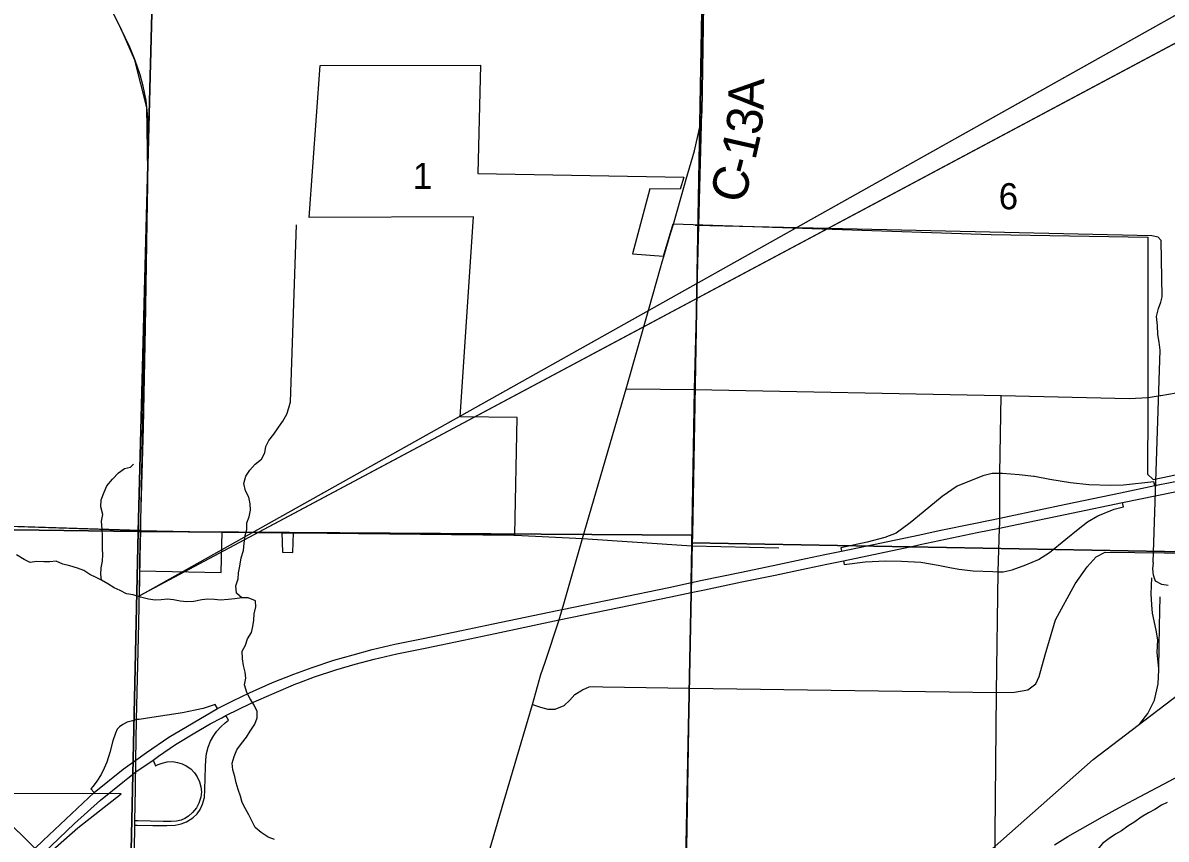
# Model space of a CAD drawing. Extents: x -6.2 to 37.4, y 0.2 to 22.2.
# Drawn here: x 2.387 to 3.302, y 17.632 to 18.286 of the extents above; entities that cross this region are included whole.
import ezdxf

# ---------------------------------------------------------------- set-up
doc = ezdxf.new("R2010")
doc.units = 0
for name, color, linetype in [('GM_X_City_Street', 7, 'Continuous'), ('GM_X_Corporation', 7, 'Continuous'), ('GM_X_County_Road', 7, 'Continuous'), ('GM_X_County_Road_Text', 7, 'Continuous'), ('GM_X_Interchange_Ramps', 7, 'Continuous'), ('GM_X_Major_River', 7, 'Continuous'), ('GM_X_Minor_River', 7, 'Continuous'), ('GM_X_Rail_Line', 7, 'Continuous'), ('GM_X_Section', 7, 'Continuous'), ('GM_X_Section_Text', 7, 'Continuous'), ('GM_X_State_Route', 7, 'Continuous'), ('GM_X_Township', 7, 'Continuous'), ('GM_X_Township_Road', 7, 'Continuous'), ('GM_X_US_Route', 7, 'Continuous'), ('SH_Border', 7, 'Continuous'), ('SH_Data', 7, 'Continuous')]:
    doc.layers.add(name, color=color, linetype=linetype)

msp = doc.modelspace()

# ---------------------------------------------------------------- linework, layer by layer
at = {"layer": 'GM_X_City_Street'}
for p, q in [((3.16884, 17.92506), (3.16991, 17.98751)), ((3.16607, 17.74978), (3.16763, 17.84647))]:
    msp.add_line(p, q, dxfattribs=at)
for points in [[(3.16763, 17.84647), (3.16861, 17.88138), (3.16871, 17.88493), (3.16872, 17.8895), (3.16884, 17.92506)], [(2.83491, 17.87314), (2.92249, 17.86721), (2.99205, 17.86569)], [(3.16607, 17.74978), (3.18054, 17.75007), (3.19114, 17.75196), (3.19758, 17.75688), (3.20022, 17.76256), (3.20515, 17.77997), (3.21347, 17.80799), (3.22899, 17.83676), (3.23883, 17.85039), (3.24602, 17.85834), (3.25321, 17.86213), (3.41908, 17.86039)], [(2.79481, 17.74032), (2.80124, 17.73804), (2.80729, 17.73653), (2.81297, 17.73653), (2.82016, 17.73956), (2.82471, 17.74372), (2.82887, 17.74827), (2.83492, 17.75205), (2.84022, 17.75432), (2.844, 17.7547), (2.8512, 17.75432), (2.92059, 17.75332), (3.16607, 17.74978)], [(3.17013, 17.59709), (3.16815, 17.59976), (3.16636, 17.60358), (3.16489, 17.60814), (3.16607, 17.74978)]]:
    msp.add_lwpolyline(points, dxfattribs=at)
at = {"layer": 'GM_X_Corporation'}
for points in [[(2.35424, 17.88385), (2.4812, 17.87984), (2.4805, 17.84719), (2.54571, 17.84588), (2.54659, 17.87851), (2.59427, 17.87785), (2.59476, 17.86207), (2.60315, 17.86191), (2.60364, 17.87785), (2.78087, 17.87604), (2.78251, 17.96992), (2.73713, 17.97057), (2.74766, 18.1307), (2.61613, 18.13005), (2.62501, 18.25171), (2.75325, 18.25204), (2.75127, 18.16523), (2.916, 18.16227), (2.91312, 18.15273), (2.88879, 18.15315), (2.8749, 18.10111), (2.89981, 18.09906), (2.90754, 18.12511), (3.16182, 18.11657), (3.28713, 18.11438), (3.28713, 17.99432), (3.28713, 17.97888), (3.28709, 17.9246), (3.29164, 17.92023), (3.41279, 17.94574)], [(2.3625, 17.65873), (2.40407, 17.61767), (2.43099, 17.64147), (2.46584, 17.66876), (2.3696, 17.66906)]]:
    msp.add_lwpolyline(points, dxfattribs=at)
at = {"layer": 'GM_X_County_Road'}
for p, q in [((2.91658, 18.15603), (2.91793, 18.16076)), ((2.89739, 18.08981), (2.89872, 18.09453)), ((2.88802, 18.05674), (2.89739, 18.08981)), ((2.35781, 17.88347), (2.48132, 17.87956)), ((2.60575, 17.87755), (2.77999, 17.87577)), ((2.82001, 17.82077), (2.83491, 17.87314))]:
    msp.add_line(p, q, dxfattribs=at)
for points in [[(2.91793, 18.16076), (2.92443, 18.18345), (2.92854, 18.20128), (2.93059, 18.2141), (2.93298, 18.36992)], [(2.90569, 18.1182), (2.90765, 18.12484), (2.91658, 18.15603)], [(2.89872, 18.09453), (2.89993, 18.09878), (2.90569, 18.1182)], [(2.83491, 17.87314), (2.86996, 17.99297), (2.88802, 18.05674)], [(2.48132, 17.87956), (2.54671, 17.87823), (2.55118, 17.87817)], [(2.55118, 17.87817), (2.59438, 17.87757), (2.59586, 17.87757)], [(2.59586, 17.87757), (2.60376, 17.87757), (2.60575, 17.87755)], [(2.77999, 17.87577), (2.78098, 17.87576), (2.83491, 17.87314)], [(2.80503, 17.77425), (2.81635, 17.8079), (2.81877, 17.8164), (2.82001, 17.82077)], [(2.77209, 17.66264), (2.79481, 17.74032), (2.80163, 17.76415), (2.80503, 17.77425)], [(3.21264, 17.62791), (3.22335, 17.6346), (3.25086, 17.65033), (3.26408, 17.65745), (3.27606, 17.66397), (3.29976, 17.67648), (3.35895, 17.70785)], [(2.67749, 17.33142), (2.71955, 17.48296), (2.72957, 17.5172), (2.74782, 17.57962), (2.77209, 17.66264)]]:
    msp.add_lwpolyline(points, dxfattribs=at)
at = {"layer": 'GM_X_Interchange_Ramps'}
for points in [[(3.16884, 17.92506), (3.1626, 17.92511), (3.15516, 17.92334), (3.13478, 17.91508), (3.12274, 17.90677), (3.10738, 17.89431), (3.097, 17.88558), (3.08578, 17.87727), (3.07675, 17.87403), (3.06276, 17.87017), (3.04153, 17.86574), (3.04211, 17.86299)], [(3.19615, 17.92271), (3.1842, 17.92422), (3.17091, 17.92505), (3.16884, 17.92506)], [(3.29278, 17.91552), (3.29217, 17.9184), (3.26789, 17.9159), (3.25728, 17.91565), (3.24017, 17.91606), (3.22529, 17.91762), (3.20884, 17.92042), (3.19666, 17.92264), (3.19615, 17.92271)], [(3.16763, 17.84647), (3.17141, 17.8464), (3.17873, 17.84812), (3.18967, 17.85191), (3.19979, 17.85618), (3.20867, 17.86186), (3.22159, 17.87255), (3.23154, 17.88053), (3.23902, 17.88637), (3.24733, 17.89122), (3.26024, 17.89673), (3.26779, 17.89853), (3.26708, 17.90192)], [(3.04372, 17.85532), (3.04433, 17.85243), (3.06104, 17.85437), (3.07757, 17.85528), (3.09015, 17.85511), (3.1057, 17.85405), (3.11943, 17.85174), (3.12883, 17.85003)], [(3.12883, 17.85003), (3.13613, 17.8487), (3.14748, 17.84722), (3.16335, 17.84681), (3.16763, 17.84647)], [(2.54284, 17.73697), (2.54113, 17.74027), (2.53695, 17.73878), (2.53148, 17.73711), (2.52498, 17.73563), (2.51496, 17.73359), (2.49037, 17.72978), (2.48021, 17.72827), (2.47804, 17.72814)], [(2.47804, 17.72814), (2.47497, 17.72728), (2.4707, 17.72598), (2.46708, 17.72422), (2.46448, 17.72236), (2.46259, 17.72044), (2.46113, 17.71725), (2.45919, 17.71104), (2.45669, 17.70176), (2.45439, 17.69404), (2.4523, 17.68922), (2.4497, 17.68407), (2.44632, 17.67899), (2.44347, 17.67479), (2.44165, 17.6726), (2.4441, 17.66976)], [(2.47686, 17.64366), (2.47868, 17.64367), (2.49107, 17.64349), (2.50243, 17.64335), (2.50888, 17.64353), (2.5138, 17.6446), (2.51811, 17.64636), (2.52307, 17.64946), (2.52647, 17.65277), (2.52911, 17.6562), (2.53097, 17.66038), (2.53236, 17.66566), (2.53282, 17.6723), (2.53319, 17.69021), (2.53347, 17.69592), (2.53398, 17.70105), (2.53544, 17.70612), (2.53736, 17.711), (2.53996, 17.7155), (2.54244, 17.71889), (2.54557, 17.72233), (2.54904, 17.72569), (2.55164, 17.72765), (2.54963, 17.73146)], [(2.49133, 17.6958), (2.49338, 17.69116), (2.49534, 17.69211), (2.49863, 17.69327), (2.50271, 17.69434), (2.50707, 17.69448), (2.51097, 17.69392), (2.5145, 17.69281), (2.51788, 17.69123), (2.52155, 17.68863), (2.52438, 17.68566), (2.52665, 17.68237), (2.52841, 17.67842), (2.52962, 17.67429), (2.52995, 17.67021), (2.52958, 17.66618), (2.52805, 17.6613), (2.52615, 17.65763), (2.52299, 17.65365), (2.51974, 17.65091), (2.51672, 17.64901), (2.51371, 17.64776), (2.50995, 17.64683), (2.50591, 17.64646), (2.49932, 17.64655), (2.479, 17.64706), (2.47682, 17.64711)]]:
    msp.add_lwpolyline(points, dxfattribs=at)
at = {"layer": 'GM_X_Major_River'}
msp.add_lwpolyline([(3.30279, 17.6619), (3.29806, 17.65956), (3.29288, 17.65625), (3.28791, 17.6535), (3.28197, 17.65002), (3.27678, 17.64633), (3.27122, 17.64283), (3.26622, 17.63914), (3.26143, 17.63639), (3.25644, 17.63289), (3.25106, 17.62901), (3.24678, 17.62379), (3.24139, 17.61915), (3.2364, 17.61584), (3.23064, 17.61216), (3.22506, 17.60753), (3.22007, 17.60303), (3.21381, 17.59803), (3.20906, 17.59362), (3.20405, 17.58955), (3.19904, 17.58529), (3.19311, 17.58199), (3.18811, 17.57849)], dxfattribs=at)
at = {"layer": 'GM_X_Minor_River'}
for points in [[(2.60115, 17.98256), (2.6062, 18.12413)], [(3.29152, 17.85393), (3.29715, 18.02377), (3.29634, 18.03024), (3.29533, 18.03651), (3.2951, 18.04354), (3.29412, 18.05076), (3.29577, 18.05737), (3.29757, 18.06227), (3.2988, 18.0666), (3.29804, 18.11157), (3.29545, 18.11447), (3.29035, 18.11533), (2.92506, 18.12379)], [(2.56223, 17.82569), (2.55807, 17.82949), (2.55741, 17.83533), (2.55929, 17.84077), (2.55964, 17.84569), (2.56075, 17.85097), (2.56173, 17.85777), (2.56362, 17.8636), (2.56418, 17.86946), (2.56513, 17.87551), (2.56624, 17.8804), (2.56621, 17.88572), (2.56827, 17.89059), (2.56919, 17.89568), (2.56897, 17.90081), (2.568, 17.90616), (2.56531, 17.91117), (2.56398, 17.91709), (2.56549, 17.92293), (2.56868, 17.92777), (2.57301, 17.93276), (2.57807, 17.93659), (2.5807, 17.94182), (2.58161, 17.94672), (2.58385, 17.95159), (2.588, 17.95678), (2.59139, 17.96179), (2.59516, 17.96718), (2.59837, 17.97278), (2.60005, 17.97766), (2.60115, 17.98256)], [(2.58854, 17.6321), (2.58349, 17.63415), (2.57791, 17.63774), (2.57291, 17.64168), (2.57024, 17.64708), (2.56792, 17.65189), (2.56523, 17.65672), (2.56273, 17.66173), (2.56119, 17.6669), (2.55945, 17.67208), (2.55792, 17.67763), (2.55675, 17.6826), (2.55502, 17.68796), (2.55462, 17.69329), (2.55631, 17.69855), (2.55838, 17.70399), (2.56195, 17.709), (2.56609, 17.714), (2.56909, 17.71884), (2.57287, 17.72442), (2.57474, 17.72948), (2.57471, 17.73461), (2.57222, 17.73981), (2.56897, 17.74484), (2.56647, 17.74985), (2.56457, 17.75598), (2.5655, 17.76127), (2.56489, 17.76603), (2.56373, 17.77138), (2.56295, 17.77671), (2.56258, 17.7828), (2.56539, 17.78783), (2.56688, 17.79291), (2.57007, 17.79775), (2.57117, 17.80265), (2.5719, 17.80775), (2.57226, 17.81286), (2.57357, 17.81832), (2.57315, 17.82327), (2.56753, 17.82553), (2.56223, 17.82569), (2.5567, 17.82472), (2.55137, 17.82431), (2.54528, 17.82374), (2.54037, 17.82427), (2.53525, 17.82462), (2.5303, 17.82401), (2.52381, 17.82269), (2.5183, 17.82248), (2.51301, 17.82302), (2.50773, 17.82413), (2.50281, 17.82447), (2.49786, 17.82405), (2.49292, 17.82383), (2.48764, 17.82456), (2.48123, 17.82608), (2.47542, 17.82816), (2.46994, 17.82889), (2.46509, 17.83151), (2.46023, 17.83374), (2.45501, 17.83675), (2.44999, 17.83975), (2.44957, 17.8447), (2.44992, 17.84962), (2.45084, 17.8549), (2.45101, 17.86021), (2.45078, 17.86496), (2.45095, 17.87008), (2.45073, 17.8754), (2.4507, 17.88033), (2.45015, 17.88699), (2.45108, 17.89247), (2.44957, 17.89858), (2.44974, 17.90408), (2.45222, 17.91027), (2.45427, 17.91533), (2.4588, 17.9205), (2.46371, 17.92566), (2.46856, 17.92912), (2.47334, 17.9303)], [(2.47334, 17.9303), (2.47569, 17.9327)], [(2.44999, 17.83975), (2.44569, 17.84197), (2.44084, 17.84439), (2.436, 17.84739), (2.43075, 17.84925), (2.42474, 17.85134), (2.41909, 17.85265), (2.41366, 17.8549), (2.40872, 17.85448), (2.40397, 17.85444), (2.3981, 17.85462), (2.39295, 17.85402), (2.38809, 17.85625), (2.38214, 17.86004)], [(3.30344, 17.83548), (3.29854, 17.83634), (3.29348, 17.8391), (3.29188, 17.84387), (3.29123, 17.84882), (3.29171, 17.85374), (3.29152, 17.85393)]]:
    msp.add_lwpolyline(points, dxfattribs=at)
at = {"layer": 'GM_X_Rail_Line'}
for points in [[(2.87203, 15.37415), (2.88287, 15.8796), (2.89299, 16.38385), (2.90519, 16.87971), (2.9053, 16.8908), (2.90604, 16.9274), (2.9062, 16.95681), (2.90667, 17.03851), (2.90688, 17.07588), (2.91357, 17.34065), (2.91378, 17.35338), (2.92047, 17.7536), (2.92175, 17.83006), (2.92181, 17.83359), (2.92189, 17.83809), (2.92238, 17.86748), (2.92464, 17.99264), (2.93048, 18.21437), (2.93287, 18.3702)], [(1.68086, 16.70625), (1.76291, 16.75192), (2.22097, 17.00557), (2.46431, 17.13956), (2.55096, 17.18814), (2.74322, 17.29341), (2.78445, 17.31777), (2.81399, 17.33433), (2.83834, 17.3483), (2.85977, 17.36258), (2.89872, 17.39571), (3.02565, 17.50711), (3.14192, 17.60631), (3.24354, 17.69623), (3.29532, 17.73582), (3.33196, 17.76367), (3.37104, 17.79348), (3.41794, 17.82281), (3.45898, 17.84626), (3.52017, 17.87663)], [(3.29596, 17.76904), (3.29461, 17.7819), (3.29516, 17.79205), (3.294, 17.79964), (3.29109, 17.81344), (3.29047, 17.8201), (3.28997, 17.82888), (3.29039, 17.84171)], [(3.29596, 17.76904), (3.29666, 17.80328), (3.29716, 17.82645)], [(3.28093, 17.72481), (3.28726, 17.73309), (3.29254, 17.74371), (3.29546, 17.75686), (3.29594, 17.76812), (3.29596, 17.76904)]]:
    msp.add_lwpolyline(points, dxfattribs=at)
at = {"layer": 'GM_X_Section'}
for points in [[(2.4295, 18.37585), (2.49258, 18.37485), (2.4793, 17.87866), (1.98357, 17.88548), (1.99044, 18.38407)], [(2.49258, 18.37485), (2.93183, 18.37016), (2.9229, 17.87578), (2.4793, 17.87866)], [(2.93183, 18.37016), (3.42888, 18.36345), (3.41696, 17.8606), (2.92261, 17.86953), (2.9229, 17.87578)], [(1.98357, 17.88548), (2.4793, 17.87866), (2.46846, 17.38053), (1.97719, 17.38234)], [(2.9229, 17.87578), (2.92261, 17.86953), (2.91294, 17.3873), (2.9126, 17.3784), (2.46846, 17.38053), (2.4793, 17.87866)], [(3.41696, 17.8606), (3.41225, 17.38056), (2.91294, 17.3873), (2.92261, 17.86953)]]:
    msp.add_lwpolyline(points, close=True, dxfattribs=at)
at = {"layer": 'GM_X_State_Route'}
for p, q in [((2.48132, 17.87956), (2.48257, 17.92478)), ((2.48079, 17.8552), (2.48132, 17.87956)), ((2.47804, 17.72814), (2.47916, 17.7721)), ((2.4772, 17.6725), (2.47735, 17.68265))]:
    msp.add_line(p, q, dxfattribs=at)
for points in [[(2.4866, 18.12645), (2.48708, 18.15623), (2.48762, 18.19993), (2.48719, 18.21037), (2.48578, 18.22385), (2.48338, 18.23515), (2.48099, 18.24439), (2.47697, 18.2557), (2.47273, 18.26635), (2.46556, 18.28146), (2.45479, 18.30288), (2.44458, 18.3244), (2.4387, 18.34038), (2.43555, 18.35136), (2.43294, 18.36484), (2.43159, 18.37825)], [(2.48257, 17.92478), (2.4836, 17.96196), (2.48523, 18.04165), (2.4866, 18.12645)], [(2.47916, 17.7721), (2.48001, 17.80531), (2.48062, 17.84691), (2.48079, 17.8552)], [(2.47735, 17.68265), (2.4774, 17.68621), (2.47755, 17.69574), (2.47804, 17.72814)], [(2.47636, 17.6237), (2.47686, 17.64366), (2.47682, 17.64711), (2.4772, 17.6725)]]:
    msp.add_lwpolyline(points, dxfattribs=at)
at = {"layer": 'GM_X_Township'}
msp.add_lwpolyline([(3.31666, 17.62007), (3.28508, 17.59881), (3.22997, 17.55435), (3.17947, 17.5104), (3.15222, 17.48363), (3.12118, 17.44688), (3.07941, 17.38888), (3.04867, 17.34024), (3.03562, 17.31049), (3.00624, 17.25417), (2.99272, 17.23206), (2.97346, 17.19773), (2.95747, 17.16618), (2.90688, 17.07588), (2.91357, 17.34065), (2.91378, 17.35338), (2.92047, 17.7536), (2.92175, 17.83006), (2.92181, 17.83359), (2.92189, 17.83809), (2.92238, 17.86748), (2.92464, 17.99264), (2.93048, 18.21437), (2.93287, 18.3702)], dxfattribs=at)
at = {"layer": 'GM_X_Township_Road'}
for p, q in [((2.86996, 17.99297), (2.92476, 17.99237)), ((2.92476, 17.99237), (3.16991, 17.98751))]:
    msp.add_line(p, q, dxfattribs=at)
for points in [[(3.29769, 17.9876), (3.30983, 17.98981), (3.36671, 18.00216), (3.42302, 18.01394)], [(3.16991, 17.98751), (3.27219, 17.98521), (3.28742, 17.98607), (3.29718, 17.98751), (3.29769, 17.9876)]]:
    msp.add_lwpolyline(points, dxfattribs=at)
at = {"layer": 'GM_X_US_Route'}
for p, q in [((3.04372, 17.85532), (3.10182, 17.86748)), ((2.49133, 17.6958), (2.4957, 17.69881)), ((2.46713, 17.67796), (2.47108, 17.68113))]:
    msp.add_line(p, q, dxfattribs=at)
for points in [[(3.26708, 17.90192), (3.29446, 17.90759), (3.33621, 17.91621), (3.40053, 17.92961), (3.42108, 17.93396), (3.43088, 17.93603), (3.48549, 17.9473), (3.51855, 17.95297), (3.55187, 17.95766), (3.58279, 17.96128), (3.60631, 17.96358), (3.62934, 17.96514), (3.64858, 17.96619)], [(2.54284, 17.73697), (2.55521, 17.74317), (2.56853, 17.74959), (2.58679, 17.7579), (2.60394, 17.7645), (2.61874, 17.76993), (2.63601, 17.7756), (2.65131, 17.78012), (2.66669, 17.78424), (2.68487, 17.78843), (2.70749, 17.79304), (2.738, 17.79937), (2.7635, 17.8048), (2.81474, 17.81557), (2.81877, 17.8164), (2.86277, 17.82544), (2.9039, 17.834), (2.922, 17.83782), (2.93079, 17.83967), (2.96081, 17.84601), (2.98738, 17.85152), (3.01353, 17.85703), (3.02883, 17.86023), (3.04211, 17.86299), (3.10479, 17.87617), (3.12036, 17.87941), (3.14924, 17.88538), (3.16872, 17.8895), (3.17623, 17.89109), (3.22171, 17.90057), (3.26534, 17.90964), (3.29278, 17.91552), (3.30913, 17.91875)], [(3.10182, 17.86748), (3.1052, 17.86819), (3.15077, 17.87782), (3.16861, 17.88138), (3.1775, 17.88316), (3.22627, 17.89344), (3.26708, 17.90192)], [(2.60786, 17.75768), (2.62035, 17.76226), (2.63762, 17.76793), (2.65292, 17.77246), (2.6683, 17.77657), (2.68648, 17.78076), (2.7091, 17.78537), (2.73961, 17.7917), (2.76511, 17.79713), (2.81635, 17.8079), (2.86438, 17.81777), (2.90551, 17.82633), (2.92187, 17.82978), (2.9324, 17.832), (2.96242, 17.83834), (2.98899, 17.84385), (3.01514, 17.84936), (3.03044, 17.85256), (3.04372, 17.85532)], [(2.54963, 17.73146), (2.56993, 17.74137), (2.58819, 17.74918), (2.60555, 17.75683), (2.60786, 17.75768)], [(2.4441, 17.66976), (2.46739, 17.68845), (2.47755, 17.69574), (2.48609, 17.70187), (2.504, 17.71421), (2.54284, 17.73697)], [(2.4957, 17.69881), (2.50923, 17.70814), (2.52478, 17.71751), (2.53695, 17.72467), (2.54625, 17.7296), (2.54963, 17.73146)], [(2.47108, 17.68113), (2.4774, 17.68621), (2.49133, 17.6958)], [(2.40335, 17.62087), (2.42845, 17.64494), (2.44934, 17.66369), (2.46713, 17.67796)], [(2.1603, 17.40255), (2.22642, 17.46302), (2.30055, 17.53366), (2.35113, 17.58153), (2.40336, 17.63129), (2.4441, 17.66976)]]:
    msp.add_lwpolyline(points, dxfattribs=at)
at = {"layer": 'SH_Border'}
for p, q in [((2.48033, 17.82715), (9.08657, 21.53204)), ((9.08657, 21.35383), (2.48033, 17.82715))]:
    msp.add_line(p, q, dxfattribs=at)
at = {"layer": 'SH_Data'}
msp.add_lwpolyline([(9.08657, 21.35383), (2.48033, 17.82715), (9.08657, 21.53204)], close=True, dxfattribs=at)
msp.add_lwpolyline([(2.48033, 17.82715), (2.48152, 17.88676), (2.48721, 18.16699), (2.48636, 18.21827), (2.47679, 18.25616), (2.46542, 18.28173), (2.44933, 18.31438), (2.4371, 18.34596), (2.43149, 18.38016), (2.432, 18.42716), (2.43323, 18.48705), (2.438, 18.71824), (2.44593, 19.03008), (2.45189, 19.31604), (2.46228, 19.97933), (2.46838, 20.33827), (2.46928, 20.38039)], dxfattribs=at)

# ---------------------------------------------------------------- texts
at = {"layer": 'GM_X_County_Road_Text'}
for s, rotation, p in [('A', 89.00714, (2.97988, 18.21604)), ('3', 82.99601, (2.97752, 18.19542)), ('1', 77.29002, (2.97314, 18.17531)), ('-', 75.20631, (2.9699, 18.16293)), ('C', 74.54942, (2.96359, 18.1401))]:
    msp.add_text(s, height=0.02841, rotation=rotation, dxfattribs=at).set_placement(p)
at = {"layer": 'GM_X_Section_Text'}
for s, p in [('1', (2.69915, 18.15291)), ('6', (3.1679, 18.13666))]:
    msp.add_text(s, height=0.02093, rotation=0.00001, dxfattribs=at).set_placement(p)

doc.saveas('drawing.dxf')
